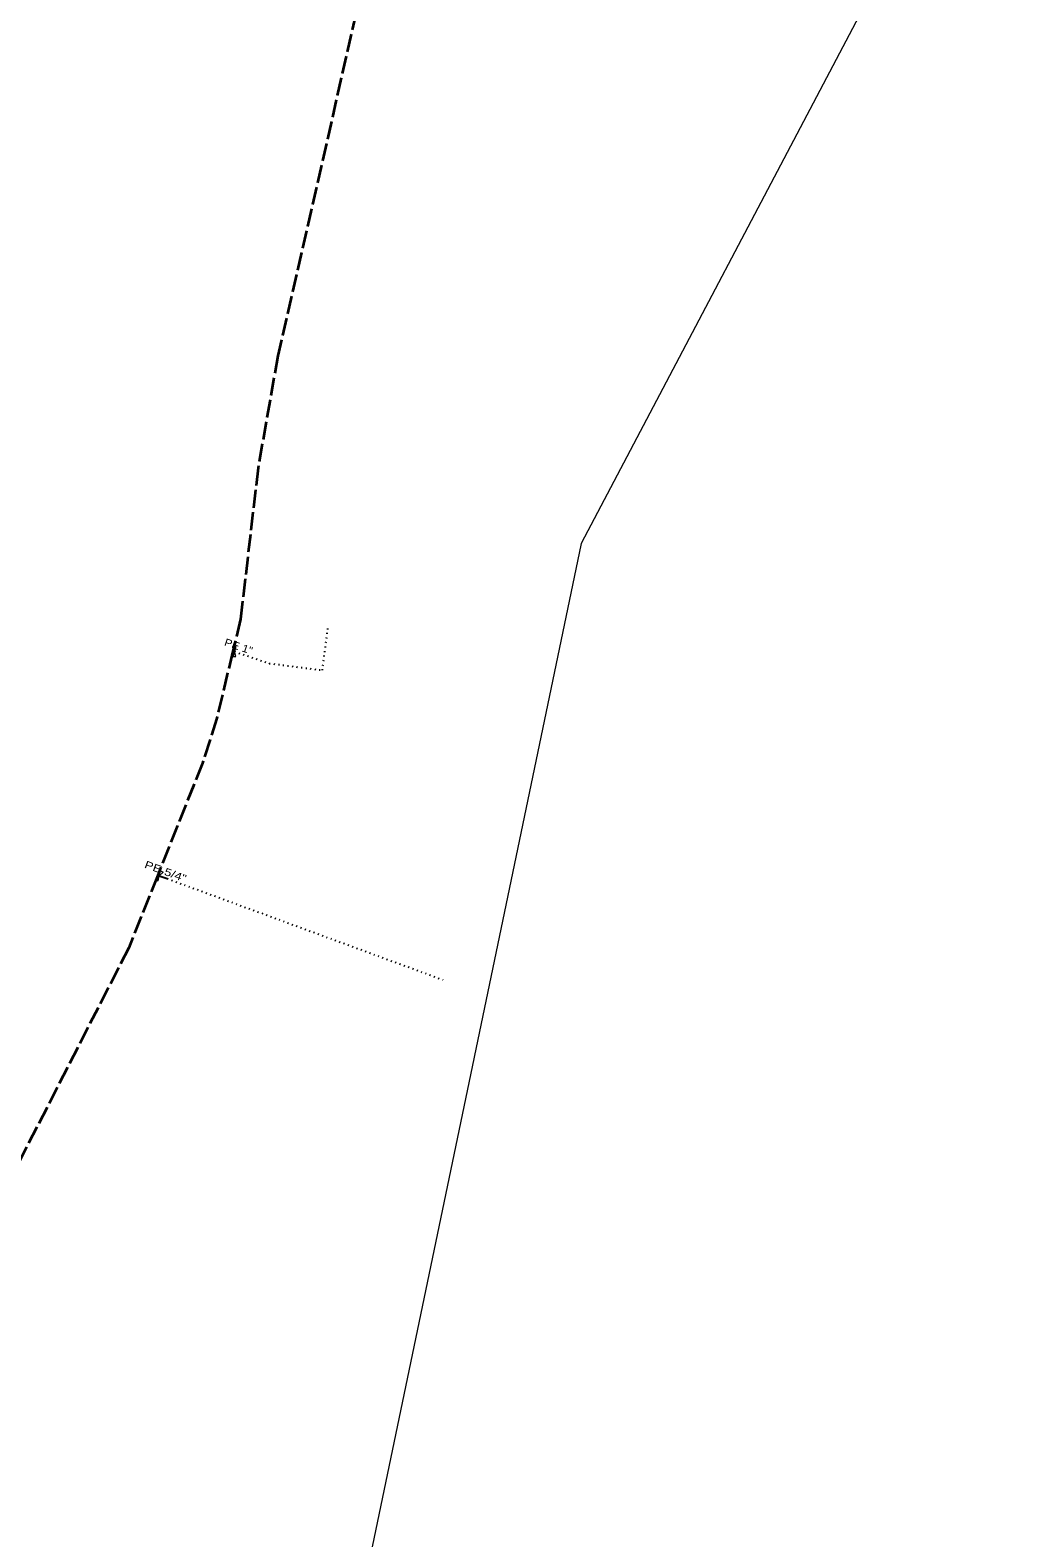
# Model space of a CAD drawing. Extents: x -582626 to -580899, y -1097611 to -1096610.
# Drawn here: x -581490.3 to -581391.1, y -1096912.4 to -1096761 of the extents above; entities that cross this region are included whole.
import ezdxf
from ezdxf.enums import TextEntityAlignment as Align

# ---------------------------------------------------------------- set-up
doc = ezdxf.new("R2010")
doc.units = 0
doc.header["$LTSCALE"] = 0.3
doc.linetypes.add('DOTTED', pattern=[1.5, 0.3, -1.2])
doc.linetypes.add('LONG_DASHED', pattern=[7.5, 6, -1.5])
for name, color, linetype, lineweight in [('1', 7, 'Continuous', 13), ('10', 7, 'Continuous', 13), ('35', 7, 'LONG_DASHED', 35), ('50', 7, 'LONG_DASHED', 25), ('51', 7, 'DOTTED', 25)]:
    doc.layers.add(name, color=color, linetype=linetype, lineweight=lineweight)
doc.layers.add('19', color=7, linetype='Continuous')

msp = doc.modelspace()

# ---------------------------------------------------------------- linework, layer by layer
at = {"layer": '1'}
msp.add_lwpolyline([(-582625.57, -1097394.66), (-582612.34, -1097467.421), (-582321.299, -1097262.369), (-581897.965, -1097202.837), (-581719.372, -1097182.994), (-581593.695, -1097110.233), (-581382.028, -1096971.327), (-581362.184, -1096819.192), (-581322.497, -1096739.817), (-581210.049, -1096733.202), (-581097.601, -1096686.9), (-580905.778, -1096719.973), (-580899.163, -1096627.369), (-581084.372, -1096614.14), (-581216.663, -1096680.285), (-581368.799, -1096686.9), (-581434.945, -1096812.577), (-581468.018, -1096971.327), (-581659.84, -1097004.4), (-581831.82, -1097110.233), (-582314.684, -1097169.765), (-582519.736, -1097295.442), (-582625.57, -1097394.66)], close=True, dxfattribs=at)
at = {"layer": '10'}
for points in [[(-581469.754, -1096823.431), (-581469.904, -1096822.931), (-581469.604, -1096822.931), (-581469.754, -1096823.431), (-581469.904, -1096823.931), (-581469.604, -1096823.931)], [(-581477.296, -1096845.95), (-581477.171, -1096845.443), (-581476.912, -1096845.596), (-581477.296, -1096845.95), (-581477.68, -1096846.304), (-581477.421, -1096846.457)]]:
    msp.add_lwpolyline(points, close=True, dxfattribs=at)
at = {"layer": '35'}
for points in [[(-581455.523, -1096750.461), (-581465.398, -1096793.715), (-581467.375, -1096804.966), (-581469.14, -1096820.168), (-581469.913, -1096823.394)], [(-581469.913, -1096823.394), (-581471.527, -1096830.127), (-581472.953, -1096834.644), (-581477.44, -1096845.878)], [(-581477.44, -1096845.878), (-581480.36, -1096853.19), (-581491.148, -1096874.263), (-581495.286, -1096882.125), (-581498.837, -1096890.731), (-581502.12, -1096907.601)]]:
    msp.add_lwpolyline(points, dxfattribs=at)
at = {"layer": '50'}
for p, q in [((-581469.754, -1096823.431), (-581469.913, -1096823.394)), ((-581477.296, -1096845.95), (-581477.44, -1096845.878)), ((-581477.296, -1096845.95), (-581476.505, -1096846.236))]:
    msp.add_line(p, q, dxfattribs=at)
at = {"layer": '51'}
msp.add_line((-581476.505, -1096846.236), (-581448.832, -1096856.392), dxfattribs=at)
msp.add_lwpolyline([(-581469.754, -1096823.431), (-581466.254, -1096824.617), (-581460.929, -1096825.306), (-581460.349, -1096820.907)], dxfattribs=at)

# ---------------------------------------------------------------- texts
at = {"layer": '19'}
for s, rotation, width, p in [('PE 1"', 341.281, 1.15, (-581469.4623, -1096823.2662)), ('PE 5/4"', 340.122, 1.3, (-581476.796, -1096845.865))]:
    msp.add_text(s, height=0.75, rotation=rotation, dxfattribs=dict(at, width=width)).set_placement(p, align=Align.CENTER)

doc.saveas('drawing.dxf')
